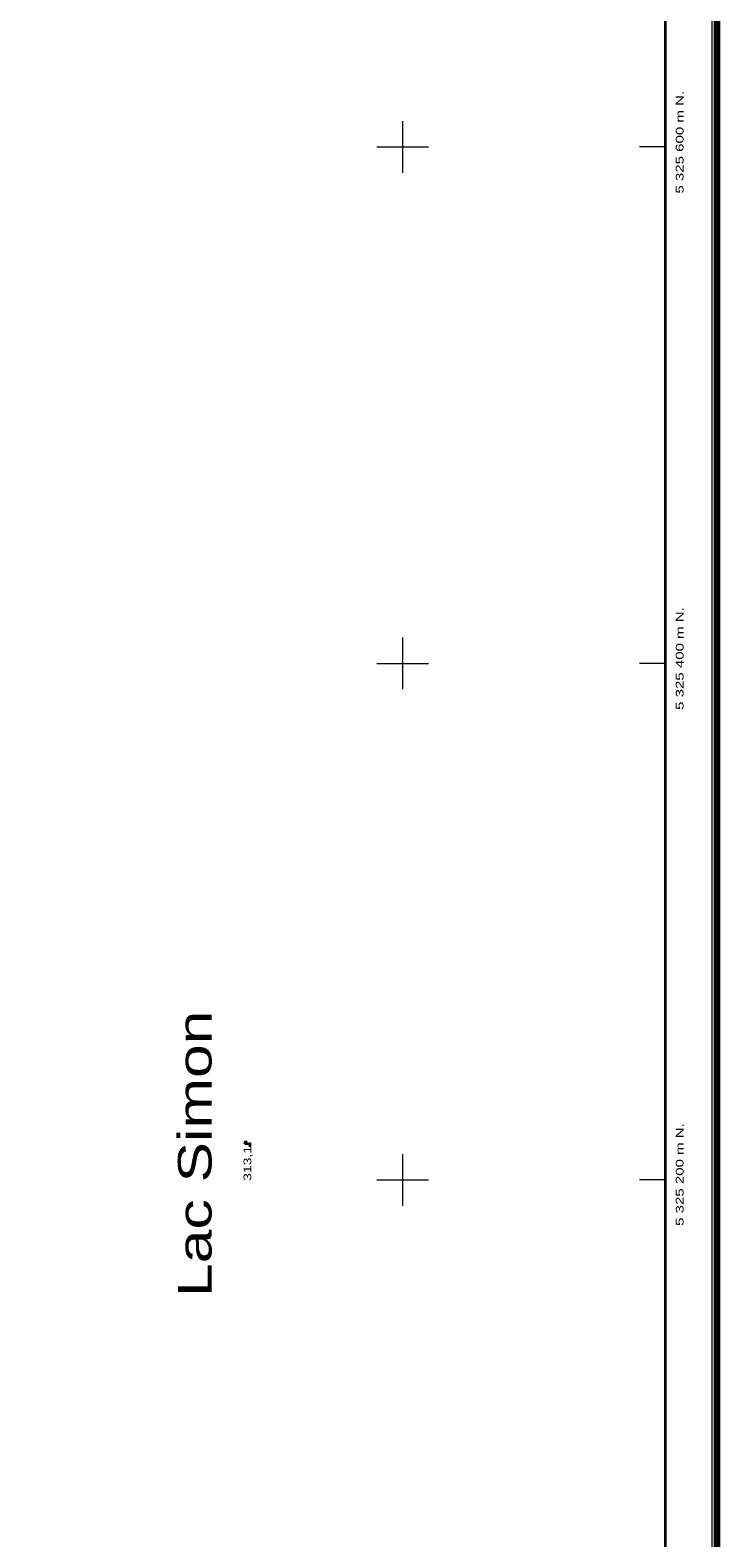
# Model space of a CAD drawing. Extents: x 240591 to 242335, y 5323482 to 5326937.
# Drawn here: x 242056 to 242322, y 5325061 to 5325645 of the extents above; entities that cross this region are included whole.
import ezdxf
from ezdxf.enums import TextEntityAlignment as Align

# ---------------------------------------------------------------- set-up
doc = ezdxf.new("R2010")
doc.units = 0
doc.header["$LTSCALE"] = 1.2
doc.linetypes.add('DASH_DOUBLE_DOT', pattern=[9.2, 5, -1.2, 0.3, -1.2, 0.3, -1.2])
for name, color, linetype, lineweight in [('3', 7, 'Continuous', 140), ('4', 7, 'DASH_DOUBLE_DOT', 53), ('60', 7, 'Continuous', 35), ('61', 7, 'Continuous', 13)]:
    doc.layers.add(name, color=color, linetype=linetype, lineweight=lineweight)

msp = doc.modelspace()

# ---------------------------------------------------------------- linework, layer by layer
at = {"layer": '3', "lineweight": 35}
for p, q in [((242138.5, 5325214.7), (242140.3, 5325214)), ((242139.4, 5325213.6), (242139.4, 5325215.2)), ((242141, 5325212.9), (242141, 5325214.5))]:
    msp.add_line(p, q, dxfattribs=at)
at = {"layer": '60', "lineweight": 158}
msp.add_lwpolyline([(242321.7, 5323482.5), (240590.8, 5323482.5), (240590.8, 5326907.9), (242321.7, 5326907.9)], close=True, dxfattribs=at)
at = {"layer": '60', "lineweight": 13}
msp.add_lwpolyline([(240592.8, 5323484.5), (240592.8, 5326905.9), (242319.7, 5326905.9), (242319.7, 5323484.5)], close=True, dxfattribs=at)
at = {"layer": '60'}
msp.add_lwpolyline([(240610.8, 5326369.9), (242301.7, 5326369.9), (242301.7, 5323502.5), (240610.8, 5323502.5)], close=True, dxfattribs=at)
at = {"layer": '61'}
for p, q in [((242301.7, 5325600), (242291.7, 5325600)), ((242301.7, 5325400), (242291.7, 5325400)), ((242301.7, 5325200), (242291.7, 5325200))]:
    msp.add_line(p, q, dxfattribs=at)
for points in [[(242200, 5325610), (242200, 5325600), (242200, 5325590)], [(242190, 5325600), (242200, 5325600), (242210, 5325600)], [(242200, 5325410), (242200, 5325400), (242200, 5325390)], [(242190, 5325400), (242200, 5325400), (242210, 5325400)], [(242200, 5325210), (242200, 5325200), (242200, 5325190)], [(242190, 5325200), (242200, 5325200), (242210, 5325200)]]:
    msp.add_lwpolyline(points, dxfattribs=at)

# ---------------------------------------------------------------- texts
at = {"layer": '3', "width": 1.35}
msp.add_text('313,1', height=3, rotation=90, dxfattribs=at).set_placement((242141.4, 5325213.2), align=Align.RIGHT)
at = {"layer": '4', "width": 1.35}
msp.add_text('Lac Simon', height=13, rotation=90, dxfattribs=at).set_placement((242126, 5325154.7))
at = {"layer": '61', "width": 1.45}
for s, p in [('5 325 600 m N.', (242308.8, 5325601.8)), ('5 325 400 m N.', (242308.8, 5325401.9)), ('5 325 200 m N.', (242308.8, 5325202.1))]:
    msp.add_text(s, height=3, rotation=90, dxfattribs=at).set_placement(p, align=Align.CENTER)

doc.saveas('drawing.dxf')
